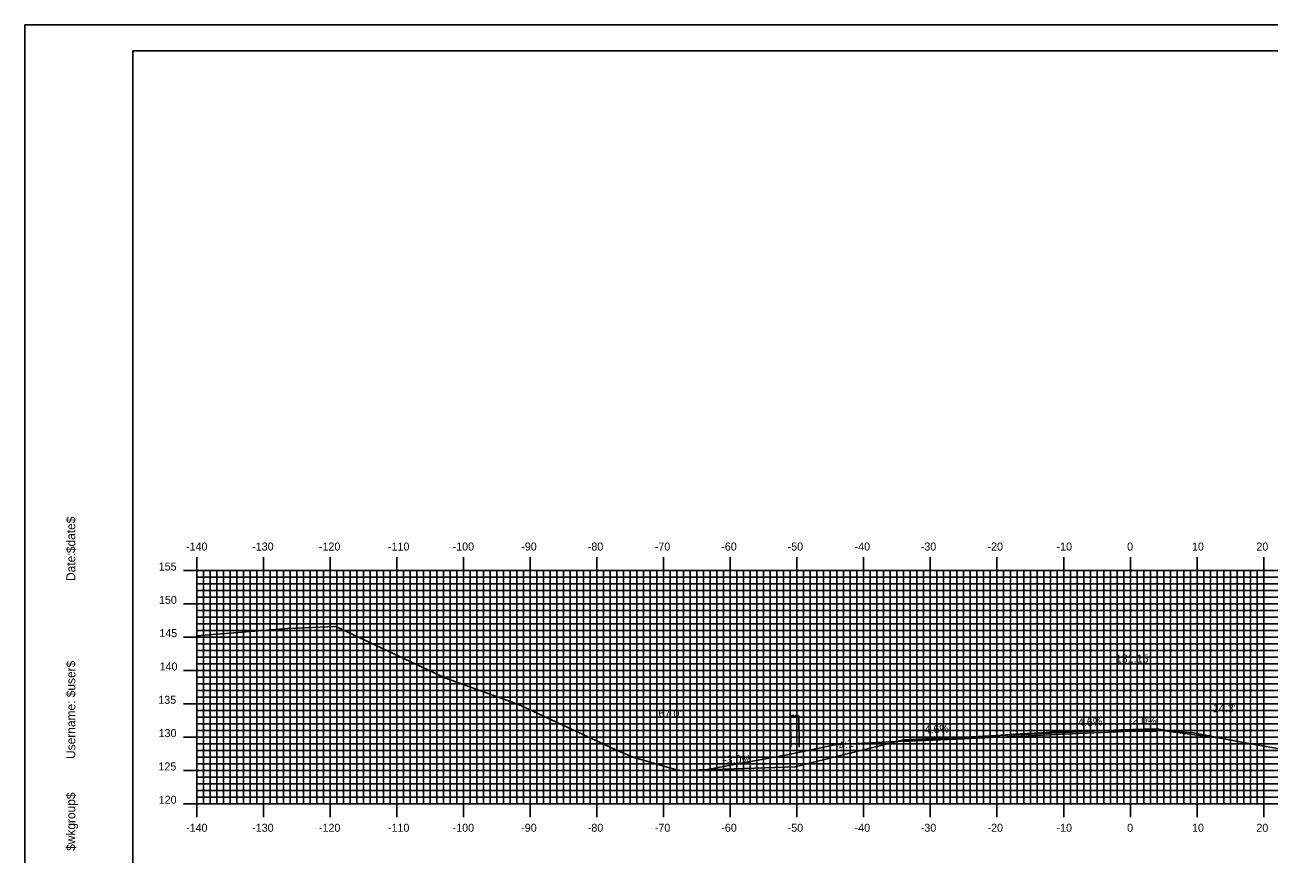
# Model space of a CAD drawing. Extents: x 850746 to 851089, y 366605 to 366825.
# Drawn here: x 850745.6 to 850932.2, y 366700.5 to 366824.9 of the extents above; entities that cross this region are included whole.
import ezdxf

# ---------------------------------------------------------------- set-up
doc = ezdxf.new("R2010")
doc.units = 0
for name, color, linetype in [('ANNOTATION', 7, 'Continuous'), ('BORDER', 7, 'Continuous'), ('D_Roadway_Centerline', 7, 'Continuous'), ('D_Roadway_Centerline_Text', 7, 'Continuous'), ('D_Roadway_Edge_Shoulder', 7, 'Continuous'), ('D_Roadway_Edge_TW', 7, 'Continuous'), ('D_Roadway_SlopeLines', 7, 'Continuous'), ('D_Text_Standard', 7, 'Continuous'), ('H_V ANNOTATION', 7, 'Continuous'), ('M_Roadway_Centerline', 7, 'Continuous'), ('MAJOR', 7, 'Continuous'), ('MINOR', 7, 'Continuous'), ('PLOT BOUNDARY', 7, 'Continuous'), ('S_Roadway_Centerline', 7, 'Continuous'), ('S_Utilities_Pole_StreetLight', 7, 'Continuous')]:
    doc.layers.add(name, color=color, linetype=linetype)

msp = doc.modelspace()

# ---------------------------------------------------------------- linework, layer by layer
at = {"layer": 'BORDER'}
msp.add_lwpolyline([(850761.83, 366611.06), (851081.83, 366611.06), (851081.83, 366821.06), (850761.83, 366821.06)], close=True, dxfattribs=at)
at = {"layer": 'D_Roadway_Centerline'}
for p, q in [((850911.42, 366719.21), (850915.42, 366719.13)), ((850915.42, 366719.13), (850925.69, 366717.78))]:
    msp.add_line(p, q, dxfattribs=at)
msp.add_lwpolyline([(850844.42, 366713.07), (850861.16, 366713.58), (850861.17, 366713.58), (850877.42, 366717.65), (850877.42, 366717.65), (850880.71, 366717.8), (850887.42, 366718.11), (850887.43, 366718.11), (850896.32, 366718.52), (850899.43, 366718.66), (850904.3, 366718.88), (850911.42, 366719.21), (850911.42, 366719.21), (850915.42, 366719.13), (850925.69, 366717.78)], dxfattribs=at)
at = {"layer": 'D_Roadway_Edge_Shoulder'}
for points in [[(850911.42, 366719.21), (850915.42, 366719.13), (850915.42, 366718.88), (850911.42, 366718.96)], [(850887.43, 366718.11), (850877.42, 366717.65), (850877.42, 366717.4), (850887.43, 366717.86)]]:
    msp.add_lwpolyline(points, close=True, dxfattribs=at)
at = {"layer": 'D_Roadway_Edge_TW'}
for points in [[(850911.42, 366719.21), (850899.43, 366718.66), (850899.43, 366718.41), (850911.42, 366718.96)], [(850899.43, 366718.66), (850887.43, 366718.11), (850887.43, 366717.86), (850899.43, 366718.41)]]:
    msp.add_lwpolyline(points, close=True, dxfattribs=at)
at = {"layer": 'D_Roadway_SlopeLines'}
for points in [[(850877.42, 366717.65), (850861.17, 366713.58)], [(850861.17, 366713.58), (850844.42, 366713.07)]]:
    msp.add_lwpolyline(points, dxfattribs=at)
at = {"layer": 'MAJOR'}
for p, q in [((850771.43, 366745.06), (850771.43, 366743.06)), ((850781.43, 366745.06), (850781.43, 366743.06)), ((850791.43, 366745.06), (850791.43, 366743.06)), ((850801.43, 366745.06), (850801.43, 366743.06)), ((850811.43, 366745.06), (850811.43, 366743.06)), ((850821.43, 366745.06), (850821.43, 366743.06)), ((850831.43, 366745.06), (850831.43, 366743.06)), ((850841.43, 366745.06), (850841.43, 366743.06)), ((850851.43, 366745.06), (850851.43, 366743.06)), ((850861.43, 366745.06), (850861.43, 366743.06)), ((850871.43, 366745.06), (850871.43, 366743.06)), ((850881.43, 366745.06), (850881.43, 366743.06)), ((850891.43, 366745.06), (850891.43, 366743.06)), ((850901.43, 366745.06), (850901.43, 366743.06)), ((850911.43, 366745.06), (850911.43, 366743.06)), ((850921.43, 366745.06), (850921.43, 366743.06)), ((850931.43, 366745.06), (850931.43, 366743.06)), ((850769.42, 366743.06), (850771.43, 366743.06)), ((850771.43, 366743.06), (851051.43, 366743.06)), ((850771.43, 366708.06), (850771.43, 366743.06)), ((850771.43, 366708.06), (850771.43, 366743.06)), ((850771.43, 366743.06), (851051.43, 366743.06)), ((850781.43, 366708.06), (850781.43, 366743.06)), ((850791.43, 366708.06), (850791.43, 366743.06)), ((850801.43, 366708.06), (850801.43, 366743.06)), ((850811.43, 366708.06), (850811.43, 366743.06)), ((850821.43, 366708.06), (850821.43, 366743.06)), ((850831.43, 366708.06), (850831.43, 366743.06)), ((850841.43, 366708.06), (850841.43, 366743.06)), ((850851.43, 366708.06), (850851.43, 366743.06)), ((850861.43, 366708.06), (850861.43, 366743.06)), ((850871.43, 366708.06), (850871.43, 366743.06)), ((850881.43, 366708.06), (850881.43, 366743.06)), ((850891.43, 366708.06), (850891.43, 366743.06)), ((850901.43, 366708.06), (850901.43, 366743.06)), ((850911.43, 366708.06), (850911.43, 366743.06)), ((850921.43, 366708.06), (850921.43, 366743.06)), ((850931.43, 366708.06), (850931.43, 366743.06)), ((850769.42, 366738.06), (850771.43, 366738.06)), ((850771.43, 366738.06), (851051.43, 366738.06)), ((850769.42, 366733.06), (850771.43, 366733.06)), ((850771.43, 366733.06), (851051.43, 366733.06)), ((850769.42, 366728.06), (850771.43, 366728.06)), ((850771.43, 366728.06), (851051.43, 366728.06)), ((850769.42, 366723.06), (850771.43, 366723.06)), ((850771.43, 366723.06), (851051.43, 366723.06)), ((850769.42, 366718.06), (850771.43, 366718.06)), ((850771.43, 366718.06), (851051.43, 366718.06)), ((850769.42, 366713.06), (850771.43, 366713.06)), ((850771.43, 366713.06), (851051.43, 366713.06)), ((850769.42, 366708.06), (850771.43, 366708.06)), ((850771.43, 366708.06), (851051.43, 366708.06)), ((850771.43, 366708.06), (851051.43, 366708.06)), ((850771.43, 366706.05), (850771.43, 366708.06)), ((850781.43, 366706.05), (850781.43, 366708.06)), ((850791.43, 366706.05), (850791.43, 366708.06)), ((850801.43, 366706.05), (850801.43, 366708.06)), ((850811.43, 366706.05), (850811.43, 366708.06)), ((850821.43, 366706.05), (850821.43, 366708.06)), ((850831.43, 366706.05), (850831.43, 366708.06)), ((850841.43, 366706.05), (850841.43, 366708.06)), ((850851.43, 366706.05), (850851.43, 366708.06)), ((850861.43, 366706.05), (850861.43, 366708.06)), ((850871.43, 366706.05), (850871.43, 366708.06)), ((850881.43, 366706.05), (850881.43, 366708.06)), ((850891.43, 366706.05), (850891.43, 366708.06)), ((850901.43, 366706.05), (850901.43, 366708.06)), ((850911.43, 366706.05), (850911.43, 366708.06)), ((850921.43, 366706.05), (850921.43, 366708.06)), ((850931.43, 366706.05), (850931.43, 366708.06))]:
    msp.add_line(p, q, dxfattribs=at)
at = {"layer": 'MINOR'}
for p, q in [((850771.43, 366742.06), (851051.43, 366742.06)), ((850771.43, 366742.06), (850773.43, 366742.06)), ((850772.43, 366708.06), (850772.43, 366743.06)), ((850773.43, 366708.06), (850773.43, 366743.06)), ((850774.43, 366708.06), (850774.43, 366743.06)), ((850775.43, 366708.06), (850775.43, 366743.06)), ((850776.43, 366708.06), (850776.43, 366743.06)), ((850777.43, 366708.06), (850777.43, 366743.06)), ((850778.43, 366708.06), (850778.43, 366743.06)), ((850779.43, 366708.06), (850779.43, 366743.06)), ((850780.43, 366708.06), (850780.43, 366743.06)), ((850782.43, 366708.06), (850782.43, 366743.06)), ((850783.43, 366708.06), (850783.43, 366743.06)), ((850784.43, 366708.06), (850784.43, 366743.06)), ((850785.43, 366708.06), (850785.43, 366743.06)), ((850786.43, 366708.06), (850786.43, 366743.06)), ((850787.43, 366708.06), (850787.43, 366743.06)), ((850788.43, 366708.06), (850788.43, 366743.06)), ((850789.43, 366708.06), (850789.43, 366743.06)), ((850790.43, 366708.06), (850790.43, 366743.06)), ((850792.43, 366708.06), (850792.43, 366743.06)), ((850793.43, 366708.06), (850793.43, 366743.06)), ((850794.43, 366708.06), (850794.43, 366743.06)), ((850795.43, 366708.06), (850795.43, 366743.06)), ((850796.43, 366708.06), (850796.43, 366743.06)), ((850797.43, 366708.06), (850797.43, 366743.06)), ((850798.43, 366708.06), (850798.43, 366743.06)), ((850799.43, 366708.06), (850799.43, 366743.06)), ((850800.43, 366708.06), (850800.43, 366743.06)), ((850802.43, 366708.06), (850802.43, 366743.06)), ((850803.43, 366708.06), (850803.43, 366743.06)), ((850804.43, 366708.06), (850804.43, 366743.06)), ((850805.43, 366708.06), (850805.43, 366743.06)), ((850806.43, 366708.06), (850806.43, 366743.06)), ((850807.43, 366708.06), (850807.43, 366743.06)), ((850808.43, 366708.06), (850808.43, 366743.06)), ((850809.43, 366708.06), (850809.43, 366743.06)), ((850810.43, 366708.06), (850810.43, 366743.06)), ((850812.43, 366708.06), (850812.43, 366743.06)), ((850813.43, 366708.06), (850813.43, 366743.06)), ((850814.43, 366708.06), (850814.43, 366743.06)), ((850815.43, 366708.06), (850815.43, 366743.06)), ((850816.43, 366708.06), (850816.43, 366743.06)), ((850817.43, 366708.06), (850817.43, 366743.06)), ((850818.43, 366708.06), (850818.43, 366743.06)), ((850819.43, 366708.06), (850819.43, 366743.06)), ((850820.43, 366708.06), (850820.43, 366743.06)), ((850822.43, 366708.06), (850822.43, 366743.06)), ((850823.43, 366708.06), (850823.43, 366743.06)), ((850824.43, 366708.06), (850824.43, 366743.06)), ((850825.43, 366708.06), (850825.43, 366743.06)), ((850826.43, 366708.06), (850826.43, 366743.06)), ((850827.43, 366708.06), (850827.43, 366743.06)), ((850828.43, 366708.06), (850828.43, 366743.06)), ((850829.43, 366708.06), (850829.43, 366743.06)), ((850830.43, 366708.06), (850830.43, 366743.06)), ((850832.43, 366708.06), (850832.43, 366743.06)), ((850833.43, 366708.06), (850833.43, 366743.06)), ((850834.43, 366708.06), (850834.43, 366743.06)), ((850835.43, 366708.06), (850835.43, 366743.06)), ((850836.43, 366708.06), (850836.43, 366743.06)), ((850837.43, 366708.06), (850837.43, 366743.06)), ((850838.43, 366708.06), (850838.43, 366743.06)), ((850839.43, 366708.06), (850839.43, 366743.06)), ((850840.43, 366708.06), (850840.43, 366743.06)), ((850842.43, 366708.06), (850842.43, 366743.06)), ((850843.43, 366708.06), (850843.43, 366743.06)), ((850844.43, 366708.06), (850844.43, 366743.06)), ((850845.43, 366708.06), (850845.43, 366743.06)), ((850846.43, 366708.06), (850846.43, 366743.06)), ((850847.43, 366708.06), (850847.43, 366743.06)), ((850848.43, 366708.06), (850848.43, 366743.06)), ((850849.43, 366708.06), (850849.43, 366743.06)), ((850850.43, 366708.06), (850850.43, 366743.06)), ((850852.43, 366708.06), (850852.43, 366743.06)), ((850853.43, 366708.06), (850853.43, 366743.06)), ((850854.43, 366708.06), (850854.43, 366743.06)), ((850855.43, 366708.06), (850855.43, 366743.06)), ((850856.43, 366708.06), (850856.43, 366743.06)), ((850857.43, 366708.06), (850857.43, 366743.06)), ((850858.43, 366708.06), (850858.43, 366743.06)), ((850859.43, 366708.06), (850859.43, 366743.06)), ((850860.43, 366708.06), (850860.43, 366743.06)), ((850862.43, 366708.06), (850862.43, 366743.06)), ((850863.43, 366708.06), (850863.43, 366743.06)), ((850864.43, 366708.06), (850864.43, 366743.06)), ((850865.43, 366708.06), (850865.43, 366743.06)), ((850866.43, 366708.06), (850866.43, 366743.06)), ((850867.43, 366708.06), (850867.43, 366743.06)), ((850868.43, 366708.06), (850868.43, 366743.06)), ((850869.43, 366708.06), (850869.43, 366743.06)), ((850870.43, 366708.06), (850870.43, 366743.06)), ((850872.43, 366708.06), (850872.43, 366743.06)), ((850873.43, 366708.06), (850873.43, 366743.06)), ((850874.43, 366708.06), (850874.43, 366743.06)), ((850875.43, 366708.06), (850875.43, 366743.06)), ((850876.43, 366708.06), (850876.43, 366743.06)), ((850877.43, 366708.06), (850877.43, 366743.06)), ((850878.43, 366708.06), (850878.43, 366743.06)), ((850879.43, 366708.06), (850879.43, 366743.06)), ((850880.43, 366708.06), (850880.43, 366743.06)), ((850882.43, 366708.06), (850882.43, 366743.06)), ((850883.43, 366708.06), (850883.43, 366743.06)), ((850884.43, 366708.06), (850884.43, 366743.06)), ((850885.43, 366708.06), (850885.43, 366743.06)), ((850886.43, 366708.06), (850886.43, 366743.06)), ((850887.43, 366708.06), (850887.43, 366743.06)), ((850888.43, 366708.06), (850888.43, 366743.06)), ((850889.43, 366708.06), (850889.43, 366743.06)), ((850890.43, 366708.06), (850890.43, 366743.06)), ((850892.43, 366708.06), (850892.43, 366743.06)), ((850893.43, 366708.06), (850893.43, 366743.06)), ((850894.43, 366708.06), (850894.43, 366743.06)), ((850895.43, 366708.06), (850895.43, 366743.06)), ((850896.43, 366708.06), (850896.43, 366743.06)), ((850897.43, 366708.06), (850897.43, 366743.06)), ((850898.43, 366708.06), (850898.43, 366743.06)), ((850899.43, 366708.06), (850899.43, 366743.06)), ((850900.43, 366708.06), (850900.43, 366743.06)), ((850902.43, 366708.06), (850902.43, 366743.06)), ((850903.43, 366708.06), (850903.43, 366743.06)), ((850904.43, 366708.06), (850904.43, 366743.06)), ((850905.43, 366708.06), (850905.43, 366743.06)), ((850906.43, 366708.06), (850906.43, 366743.06)), ((850907.43, 366708.06), (850907.43, 366743.06)), ((850908.43, 366708.06), (850908.43, 366743.06)), ((850909.43, 366708.06), (850909.43, 366743.06)), ((850910.43, 366708.06), (850910.43, 366743.06)), ((850912.43, 366708.06), (850912.43, 366743.06)), ((850913.43, 366708.06), (850913.43, 366743.06)), ((850914.43, 366708.06), (850914.43, 366743.06)), ((850915.43, 366708.06), (850915.43, 366743.06)), ((850916.43, 366708.06), (850916.43, 366743.06)), ((850917.43, 366708.06), (850917.43, 366743.06)), ((850918.43, 366708.06), (850918.43, 366743.06)), ((850919.43, 366708.06), (850919.43, 366743.06)), ((850920.43, 366708.06), (850920.43, 366743.06)), ((850922.43, 366708.06), (850922.43, 366743.06)), ((850923.43, 366708.06), (850923.43, 366743.06)), ((850924.43, 366708.06), (850924.43, 366743.06)), ((850925.43, 366708.06), (850925.43, 366743.06)), ((850926.43, 366708.06), (850926.43, 366743.06)), ((850927.43, 366708.06), (850927.43, 366743.06)), ((850928.43, 366708.06), (850928.43, 366743.06)), ((850929.43, 366708.06), (850929.43, 366743.06)), ((850930.43, 366708.06), (850930.43, 366743.06)), ((850771.43, 366741.06), (851051.43, 366741.06)), ((850771.43, 366741.06), (850773.43, 366741.06)), ((850771.43, 366740.06), (851051.43, 366740.06)), ((850771.43, 366740.06), (850773.43, 366740.06)), ((850771.43, 366739.06), (851051.43, 366739.06)), ((850771.43, 366739.06), (850773.43, 366739.06)), ((850771.43, 366737.06), (851051.43, 366737.06)), ((850771.43, 366737.06), (850773.43, 366737.06)), ((850771.43, 366736.06), (851051.43, 366736.06)), ((850771.43, 366736.06), (850773.43, 366736.06)), ((850771.43, 366735.06), (851051.43, 366735.06)), ((850771.43, 366735.06), (850773.43, 366735.06)), ((850771.43, 366734.06), (851051.43, 366734.06)), ((850771.43, 366734.06), (850773.43, 366734.06)), ((850771.43, 366732.06), (851051.43, 366732.06)), ((850771.43, 366732.06), (850773.43, 366732.06)), ((850771.43, 366731.06), (851051.43, 366731.06)), ((850771.43, 366731.06), (850773.43, 366731.06)), ((850771.43, 366730.06), (851051.43, 366730.06)), ((850771.43, 366730.06), (850773.43, 366730.06)), ((850771.43, 366729.06), (851051.43, 366729.06)), ((850771.43, 366729.06), (850773.43, 366729.06)), ((850771.43, 366727.06), (851051.43, 366727.06)), ((850771.43, 366727.06), (850773.43, 366727.06)), ((850771.43, 366726.06), (851051.43, 366726.06)), ((850771.43, 366726.06), (850773.43, 366726.06)), ((850771.43, 366725.06), (851051.43, 366725.06)), ((850771.43, 366725.06), (850773.43, 366725.06)), ((850771.43, 366724.06), (851051.43, 366724.06)), ((850771.43, 366724.06), (850773.43, 366724.06)), ((850771.43, 366722.06), (851051.43, 366722.06)), ((850771.43, 366722.06), (850773.43, 366722.06)), ((850771.43, 366721.06), (851051.43, 366721.06)), ((850771.43, 366721.06), (850773.43, 366721.06)), ((850771.43, 366720.06), (851051.43, 366720.06)), ((850771.43, 366720.06), (850773.43, 366720.06)), ((850771.43, 366719.06), (851051.43, 366719.06)), ((850771.43, 366719.06), (850773.43, 366719.06)), ((850771.43, 366717.06), (851051.43, 366717.06)), ((850771.43, 366717.06), (850773.43, 366717.06)), ((850771.43, 366716.06), (851051.43, 366716.06)), ((850771.43, 366716.06), (850773.43, 366716.06)), ((850771.43, 366715.06), (851051.43, 366715.06)), ((850771.43, 366715.06), (850773.43, 366715.06)), ((850771.43, 366714.06), (851051.43, 366714.06)), ((850771.43, 366714.06), (850773.43, 366714.06)), ((850771.43, 366712.06), (851051.43, 366712.06)), ((850771.43, 366712.06), (850773.43, 366712.06)), ((850771.43, 366711.06), (851051.43, 366711.06)), ((850771.43, 366711.06), (850773.43, 366711.06)), ((850771.43, 366710.06), (851051.43, 366710.06)), ((850771.43, 366710.06), (850773.43, 366710.06)), ((850771.43, 366709.06), (851051.43, 366709.06)), ((850771.43, 366709.06), (850773.43, 366709.06))]:
    msp.add_line(p, q, dxfattribs=at)
at = {"layer": 'PLOT BOUNDARY'}
msp.add_lwpolyline([(850745.64, 366604.94), (851085.64, 366604.94), (851085.64, 366824.94), (850745.64, 366824.94)], close=True, dxfattribs=at)
at = {"layer": 'S_Roadway_Centerline'}
msp.add_lwpolyline([(850771.43, 366733.28), (850785.03, 366734.38), (850792.27, 366734.66), (850808.64, 366726.98), (850819.68, 366722.96), (850834.17, 366716.22), (850836.8, 366715.04), (850843.37, 366713.16), (850844.42, 366713.07), (850847.95, 366713.19), (850859.95, 366715.4), (850867.11, 366716.9), (850868.5, 366716.98), (850885.57, 366717.91), (850885.97, 366717.93), (850886.09, 366717.94), (850894.89, 366718.53), (850898.04, 366718.69), (850899.59, 366718.81), (850901.81, 366718.8), (850903.33, 366718.87), (850910.05, 366719.13), (850915.34, 366719.3), (850918.02, 366718.92), (850920.94, 366718.68), (850928.35, 366717.27), (850938.64, 366715.45)], dxfattribs=at)
at = {"layer": 'S_Utilities_Pole_StreetLight'}
for p, q in [((850860.49, 366716.55), (850860.48, 366721.17)), ((850860.49, 366721.17), (850860.64, 366721.28)), ((850860.95, 366721.28), (850861.11, 366721.17)), ((850861.27, 366721.28), (850861.11, 366721.17)), ((850861.11, 366721.17), (850861.27, 366721.06)), ((850861.74, 366721.17), (850861.58, 366721.28)), ((850861.58, 366721.06), (850861.74, 366721.17)), ((850861.74, 366716.55), (850861.73, 366721.17))]:
    msp.add_line(p, q, dxfattribs=at)
for centre, start, end in [((850860.8, 366721.06), 90, 125.2644), ((850860.8, 366721.06), 54.7356, 90), ((850861.42, 366721.06), 90, 125.2644), ((850861.42, 366721.28), 234.7356, 270), ((850861.42, 366721.06), 54.7356, 90), ((850861.42, 366721.28), 270, 305.2644)]:
    msp.add_arc(centre, 0.271, start, end, dxfattribs=at)

# ---------------------------------------------------------------- texts
at = {"layer": 'ANNOTATION'}
for s, rotation, p in [('-2.0%', 357.7098, (850911.15, 366720.02)), ('-4.6%', 2.6336, (850880.06, 366718.57)), ('-4.6%', 2.6338, (850903.07, 366719.63)), ('4:1', 14.0374, (850867.83, 366716.11)), ('-3.0%', 1.7376, (850850.37, 366714.06))]:
    msp.add_text(s, height=1.2, rotation=rotation, dxfattribs=at).set_placement(p)
at = {"layer": 'BORDER'}
for s, p in [('$date$', (850753.2, 366745.67)), ('Date:', (850753.2, 366741.49)), ('$user$', (850753.2, 366724.04)), ('Username:', (850753.2, 366714.79)), ('$wkgroup$', (850753.2, 366700.99))]:
    msp.add_text(s, height=1.339, rotation=90, dxfattribs=at).set_placement(p)
at = {"layer": 'D_Roadway_Centerline_Text'}
msp.add_text('131.15', height=1.2, dxfattribs=at).set_placement((850909.24, 366729.24))
at = {"layer": 'D_Text_Standard'}
for s, p in [("14.3'", (850923.8, 366721.8)), ("67.0'", (850840.67, 366721))]:
    msp.add_text(s, height=1.2, dxfattribs=at).set_placement(p)
at = {"layer": 'H_V ANNOTATION'}
for s, p in [('-140', (850769.81, 366746.06)), ('-130', (850779.73, 366746.06)), ('-120', (850789.74, 366746.06)), ('-110', (850800.09, 366746.06)), ('-100', (850809.79, 366746.06)), ('-90', (850820.08, 366746.06)), ('-80', (850830.06, 366746.06)), ('-70', (850840.11, 366746.06)), ('-60', (850850.08, 366746.06)), ('-50', (850860.03, 366746.06)), ('-40', (850870.08, 366746.06)), ('-30', (850880, 366746.06)), ('-20', (850890.01, 366746.06)), ('-10', (850900.36, 366746.06)), ('0', (850910.94, 366746.06)), ('10', (850920.68, 366746.06)), ('20', (850930.33, 366746.06)), ('155', (850765.72, 366743.06)), ('150', (850765.75, 366738.06)), ('145', (850765.8, 366733.06)), ('140', (850765.84, 366728.06)), ('135', (850765.65, 366723.06)), ('130', (850765.69, 366718.06)), ('125', (850765.67, 366713.06)), ('120', (850765.71, 366708.06)), ('-140', (850769.81, 366703.86)), ('-130', (850779.73, 366703.86)), ('-120', (850789.74, 366703.86)), ('-110', (850800.09, 366703.86)), ('-100', (850809.79, 366703.86)), ('-90', (850820.08, 366703.86)), ('-80', (850830.06, 366703.86)), ('-70', (850840.11, 366703.86)), ('-60', (850850.08, 366703.86)), ('-50', (850860.03, 366703.86)), ('-40', (850870.08, 366703.86)), ('-30', (850880, 366703.86)), ('-20', (850890.01, 366703.86)), ('-10', (850900.36, 366703.86)), ('0', (850910.94, 366703.86)), ('10', (850920.68, 366703.86)), ('20', (850930.33, 366703.86))]:
    msp.add_text(s, height=1.2, dxfattribs=at).set_placement(p)
at = {"layer": 'M_Roadway_Centerline'}
for s, p in [('C', (850899.58, 366718.81)), ('L', (850899.59, 366718.8))]:
    msp.add_text(s, height=0.0146, dxfattribs=at).set_placement(p)
at = {"layer": 'MAJOR'}
msp.add_text('-', height=0.012, dxfattribs=at).set_placement((850771.42, 366708.06))

doc.saveas('drawing.dxf')
